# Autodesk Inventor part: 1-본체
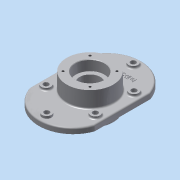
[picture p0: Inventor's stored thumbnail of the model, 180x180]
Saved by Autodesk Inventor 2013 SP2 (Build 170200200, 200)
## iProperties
Created: 2015-02
Part Number: 1-본체
Material: 알루미늄 6061
Document SubType Name: Modeling
Designer: dgall
Density: 2.71 g/cm^3
Mass: 1636.79 g
Surface Area: 926.654 cm^2
Volume: 603.98 cm^3
Author: dgall
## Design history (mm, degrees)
sketch "스케치2"
  geometry: L1 (-70, 60)-(-70, -60); L2 (-70, -60)-(70, -60); L3 (70, -60)-(70, 60); L4 (70, 60)-(-70, 60); A1 r 74 centre (0, 36) between (70, 60) and (-70, 60); A2 r 74 centre (0, -36) between (-70, -60) and (70, -60); 3 further points
  constraints: 8 end point, 4 point on circle, 3 vertical alignment, 2 centre point, 2 midpoint, 2 parallel, 1 horizontal alignment, 1 perpendicular, 1 vertical
  dimensions: "d4" = 140 distance of L1.end L2.end; "d6" = 120 distance of L2.end L3.end; "d7" = 50 distance edge to line of A1 L4; "d8" = 50 distance edge to line of A2 L2
extrude "돌출1" new body sketch "스케치2" distance "d9" = 12; taper "d10" = 0 deg
fillet "모깎기1" dims "d11" = 3
sketch "스케치3"
  geometry: C1 r 50 at (0, 0); 1 further point
  constraints: 1 centre point, 1 coincident
  dimensions: "d12" = 100 diameter of C1
extrude "돌출2" join sketch "스케치3" distance "d14" = 35; taper "d15" = 0 deg
sketch "스케치4"
  geometry: C1 r 50 at (0, 0); 1 further point
  constraints: 1 centre point, 1 coincident
  dimensions: "d16" = 100 diameter of C1
extrude "돌출3" join sketch "스케치4" distance "d18" = 23; taper "d19" = 0 deg
sketch "스케치5"
  geometry: C1 r 50 at (0, 0) reference; C2 r 31 at (0, 0)
  constraints: 1 centre point, 1 coincident
  dimensions: "d20" = 62 diameter of C2
extrude "돌출4" cut sketch "스케치5" distance "d22" = 22; taper "d23" = 0 deg
sketch "스케치6"
  geometry: C1 r 50 at (0, 0) reference; C2 r 31 at (0, 0)
  constraints: 1 centre point, 1 coincident
  dimensions: "d24" = 62 diameter of C2
extrude "돌출5" cut sketch "스케치6" distance "d26" = 22; taper "d27" = 0 deg
sketch "스케치7"
  geometry: C1 r 31 at (0, 0) reference; C2 r 22.5 at (0, 0)
  constraints: 1 centre point, 1 coincident
  dimensions: "d28" = 45 diameter of C2
extrude "돌출6" cut sketch "스케치7" stored distance "d30" = 22; taper "d31" = 0 deg
sketch "스케치8"
  geometry: L1 (0, 0)-(22.5, 0); L2 (0, 0)-(28.991, 28.991); C1 r 31 at (0, 0) reference; 2 further points
  constraints: 4 end point, 1 coincident, 1 horizontal, 1 horizontal alignment, 1 other
  dimensions: "d33" = 41 distance of L1.start L2.end; "d35" = 45 deg angle of L1 L2
hole "구멍1" sketch "스케치8" at (28.991, 28.991) diameter "d37" = 4.917; stored, may be unused: countersink angle "d41" = 90 deg, drill point angle "d43" = 118 deg; dims "d38" = 10, "d39" = 4, "d40" = 2, "d42" = 13
node "작업 평면1"
fillet "모깎기2" dims "d47" = 0.3
chamfer "모따기1" distance "d48" = 1; stored, may be unused: second distance "d49" = 2, angle "d50" = 45 deg
node "작업 평면2"
sketch "스케치9"
  geometry: 2 further points
  constraints: 1 vertical alignment, 1 other
  dimensions: "d52" = 65 distance of point (0, 0) point (0, 65)
feature "엠보싱1" sketch "스케치9" dims "d16" = 100, "d53" = 1, "d54" = 0
fillet "모깎기3" dims "d55" = 3
sketch "스케치10"
  geometry: L1 (-67, -59.495)-(-67, 59.495) reference; L2 (67, 59.495)-(67, -59.495) reference; L3 (-53, -56.976)-(-53, 56.976); L4 (53, 56.976)-(53, -56.976); L5 (70, -60)-(70, 60) reference; C1 r 10 at (0, -93); C2 r 10 at (0, 93); C3 r 10 at (53, -41.5); C4 r 10 at (-53, -41.5); C5 r 10 at (-53, 41.5); C6 r 10 at (53, 41.5); C7 r 53 at (0, 0) reference; A1 r 71 centre (0, 36) between (67, 59.495) and (-67, 59.495) reference; A2 r 71 centre (0, -36) between (-67, -59.495) and (67, -59.495) reference; A3 r 57 centre (0, -36) between (-53, -56.976) and (53, -56.976); A4 r 57 centre (0, 36) between (53, 56.976) and (-53, 56.976)
  constraints: 8 centre point, 6 point on circle, 4 end point, 4 point on line, 2 equal radius, 2 horizontal alignment, 3 other
  dimensions: "d56" = 17 distance between parallel lines of L4 L5; "d57" = 20 diameter of C2; "d59" = 20 diameter of C5; "d61" = 20 diameter of C4; "d62" = 20 diameter of C6; "d125" = 83 distance of C4.centre C5.centre; "d126" = 41.5 vertical distance of C7.centre C4.centre (= 0.5 x d125)
extrude "돌출7" join sketch "스케치10" distance "d63" = 5; taper "d64" = 0 deg
hole "구멍2" diameter "d67" = 11; stored, may be unused: countersink angle "d71" = 90 deg, drill point angle "d73" = 0 deg; dims "d68" = 10, "d69" = 4, "d70" = 2, "d72" = 13, "d92" = 10, "d93" = 10
hole "구멍3" diameter "d76" = 11; stored, may be unused: countersink angle "d80" = 90 deg, drill point angle "d82" = 0 deg; dims "d77" = 10, "d78" = 4, "d79" = 2, "d81" = 13, "d94" = 10, "d95" = 10
hole "구멍4" diameter "d85" = 11; stored, may be unused: countersink angle "d89" = 90 deg, drill point angle "d91" = 0 deg; dims "d86" = 10, "d87" = 4, "d88" = 2, "d90" = 13, "d96" = 10, "d97" = 10
hole "구멍5" diameter "d100" = 11; stored, may be unused: countersink angle "d104" = 90 deg, drill point angle "d106" = 0 deg; dims "d98" = 10, "d99" = 10, "d101" = 10, "d102" = 4, "d103" = 2, "d105" = 13
hole "구멍6" diameter "d109" = 11; stored, may be unused: countersink angle "d113" = 90 deg, drill point angle "d115" = 0 deg; dims "d107" = 10, "d108" = 10, "d110" = 10, "d111" = 4, "d112" = 2, "d114" = 13
hole "구멍7" diameter "d118" = 11; stored, may be unused: countersink angle "d122" = 90 deg, drill point angle "d124" = 0 deg; dims "d116" = 10, "d117" = 10, "d119" = 10, "d120" = 4, "d121" = 2, "d123" = 13
fillet "모깎기4" dims "d127" = 3
fillet "모깎기5" dims "d128" = 3
node "솔리드1"
pattern_circular "원형 패턴1" dims angle "d45" = 360 deg
mirror "대칭1"
node "투영된 루프1"
